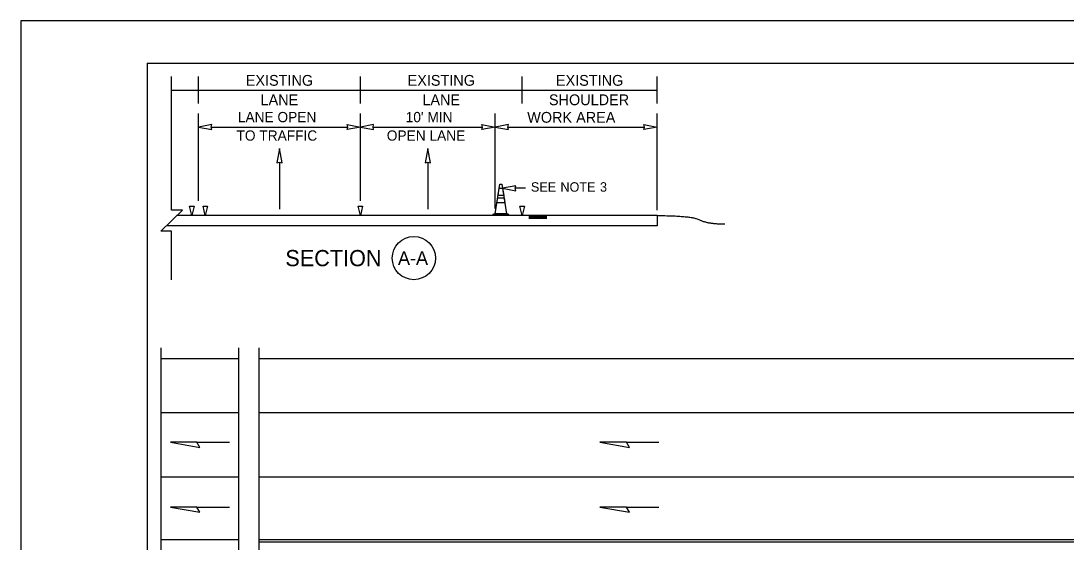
# Model space of a CAD drawing. Extents: x 99999.1 to 100096.1, y 99995 to 100010.7.
# Drawn here: x 100059.06 to 100066.81, y 100006.83 to 100010.69 of the extents above; entities that cross this region are included whole.
import ezdxf

# ---------------------------------------------------------------- set-up
doc = ezdxf.new("R2010")
doc.units = 0
for name, color, linetype in [('RD_ED_ShoulderPavedEdge', 7, 'Continuous'), ('RD_MK_LineEdgeWhite', 7, 'Continuous'), ('RD_MK_LineLane', 7, 'Continuous'), ('RD_MK_LineTwoWayLtTurn', 7, 'Continuous'), ('SH_GI_PlotLimits', 7, 'Continuous'), ('SH_GI_SheetBorder', 7, 'Continuous'), ('SH_TI_WZSectionCut', 7, 'Continuous'), ('TR_WZ_ArrowLeftStrRightTurn', 7, 'Continuous'), ('TR_WZ_TrafficConeElev', 7, 'Continuous'), ('TR_WZ_WorkZoneDetails', 7, 'Continuous'), ('TR_WZ_WorkZoneTextCurrent', 7, 'Continuous')]:
    doc.layers.add(name, color=color, linetype=linetype)

msp = doc.modelspace()

# ---------------------------------------------------------------- linework, layer by layer
at = {"layer": 'RD_ED_ShoulderPavedEdge'}
for p, q in [((100060.1016, 100008.1857), (100060.6783, 100008.1857)), ((100060.8283, 100008.1857), (100074.8933, 100008.1857))]:
    msp.add_line(p, q, dxfattribs=at)
at = {"layer": 'RD_MK_LineEdgeWhite'}
for p, q in [((100060.1016, 100007.7857), (100060.6783, 100007.7857)), ((100060.8283, 100007.7857), (100074.8933, 100007.7857))]:
    msp.add_line(p, q, dxfattribs=at)
at = {"layer": 'RD_MK_LineLane'}
for points in [[(100060.6783, 100007.3057), (100060.1016, 100007.3057)], [(100060.6783, 100007.3057), (100060.1016, 100007.3057)], [(100074.8933, 100007.3057), (100060.8283, 100007.3057)]]:
    msp.add_lwpolyline(points, dxfattribs=at)
at = {"layer": 'RD_MK_LineTwoWayLtTurn'}
for p, q in [((100060.1016, 100006.8457), (100060.6783, 100006.8457)), ((100060.8283, 100006.8457), (100074.914, 100006.8457))]:
    msp.add_line(p, q, dxfattribs=at)
msp.add_lwpolyline([(100074.8933, 100006.8257), (100060.8283, 100006.8257)], dxfattribs=at)
at = {"layer": 'SH_GI_PlotLimits'}
msp.add_lwpolyline([(100059.0625, 99999.6875), (100076.0625, 99999.6875), (100076.0625, 100010.6875), (100059.0625, 100010.6875)], close=True, dxfattribs=at)
at = {"layer": 'SH_GI_SheetBorder'}
for q in [(100060, 100000), (100075.75, 100010.375)]:
    msp.add_line((100060, 100010.375), q, dxfattribs=at)
at = {"layer": 'SH_TI_WZSectionCut'}
for p, q in [((100060.38, 100010.075), (100060.38, 100010.275)), ((100061.58, 100010.075), (100061.58, 100010.275)), ((100062.78, 100010.075), (100062.78, 100010.275)), ((100063.78, 100010.075), (100063.78, 100010.275)), ((100060.18, 100010.175), (100060.38, 100010.175)), ((100060.38, 100010.175), (100061.58, 100010.175)), ((100061.58, 100010.175), (100062.78, 100010.175)), ((100062.78, 100010.175), (100063.78, 100010.175)), ((100060.38, 100009.3547), (100060.38, 100010.001)), ((100061.58, 100009.3547), (100061.58, 100010.001)), ((100062.58, 100009.2975), (100062.58, 100010.001)), ((100063.78, 100009.2849), (100063.78, 100010.001)), ((100060.4738, 100009.901), (100061.4863, 100009.901)), ((100061.6738, 100009.901), (100062.4863, 100009.901)), ((100062.6738, 100009.901), (100063.6863, 100009.901)), ((100063.78, 100009.2449), (100060.2188, 100009.2449)), ((100062.963, 100009.2393), (100062.83, 100009.2393)), ((100062.963, 100009.2337), (100062.83, 100009.2337)), ((100062.963, 100009.228), (100062.83, 100009.228)), ((100062.963, 100009.2228), (100062.83, 100009.2228)), ((100063.78, 100009.2449), (100063.78, 100009.1699)), ((100063.78, 100009.1699), (100060.1413, 100009.1699))]:
    msp.add_line(p, q, dxfattribs=at)
for points in [[(100060.38, 100009.901), (100060.4783, 100009.8817), (100060.4738, 100009.901), (100060.4783, 100009.9203)], [(100061.58, 100009.901), (100061.4817, 100009.8817), (100061.4863, 100009.901), (100061.4817, 100009.9203)], [(100061.58, 100009.901), (100061.6783, 100009.8817), (100061.6738, 100009.901), (100061.6783, 100009.9203)], [(100062.58, 100009.901), (100062.4817, 100009.8817), (100062.4863, 100009.901), (100062.4817, 100009.9203)], [(100062.58, 100009.901), (100062.6783, 100009.8817), (100062.6738, 100009.901), (100062.6783, 100009.9203)], [(100063.78, 100009.901), (100063.6817, 100009.8817), (100063.6863, 100009.901), (100063.6817, 100009.9203)], [(100060.3133, 100009.3147), (100060.3467, 100009.3147), (100060.33, 100009.2449)], [(100060.4133, 100009.3147), (100060.4467, 100009.3147), (100060.43, 100009.2449)], [(100061.5634, 100009.3147), (100061.5967, 100009.3147), (100061.5801, 100009.2449)], [(100062.7634, 100009.3147), (100062.7967, 100009.3147), (100062.7801, 100009.2449)]]:
    msp.add_lwpolyline(points, close=True, dxfattribs=at)
msp.add_circle((100061.9766, 100008.93), 0.16, dxfattribs=at)
msp.add_open_spline([(100063.78, 100009.2449), (100064.0312, 100009.2451), (100064.1567, 100009.183), (100064.2822, 100009.1831)], degree=2, dxfattribs=at)
at = {"layer": 'TR_WZ_ArrowLeftStrRightTurn'}
for p, q in [((100060.98, 100009.6418), (100060.98, 100009.292)), ((100062.08, 100009.6418), (100062.08, 100009.292))]:
    msp.add_line(p, q, dxfattribs=at)
for points in [[(100060.98, 100009.742), (100060.9594, 100009.6369), (100060.98, 100009.6418), (100061.0006, 100009.6369)], [(100062.08, 100009.742), (100062.0594, 100009.6369), (100062.08, 100009.6418), (100062.1006, 100009.6369)]]:
    msp.add_lwpolyline(points, close=True, dxfattribs=at)
at = {"layer": 'TR_WZ_TrafficConeElev'}
for p, q in [((100062.6008, 100009.3929), (100062.6091, 100009.4471)), ((100062.6091, 100009.4471), (100062.6343, 100009.4471)), ((100062.6343, 100009.4471), (100062.6426, 100009.3929)), ((100062.5925, 100009.3388), (100062.5982, 100009.3763)), ((100062.6509, 100009.3388), (100062.5925, 100009.3388)), ((100062.5982, 100009.3763), (100062.6452, 100009.3763)), ((100062.6426, 100009.3929), (100062.6008, 100009.3929)), ((100062.6452, 100009.3763), (100062.6509, 100009.3388)), ((100062.5639, 100009.2533), (100062.5681, 100009.2575)), ((100062.5639, 100009.245), (100062.5639, 100009.2533)), ((100062.6634, 100009.2575), (100062.6753, 100009.2575)), ((100062.6753, 100009.2575), (100062.6795, 100009.2533)), ((100062.6795, 100009.2533), (100062.6795, 100009.245)), ((100062.6795, 100009.245), (100062.5639, 100009.245))]:
    msp.add_line(p, q, dxfattribs=at)
msp.add_lwpolyline([(100062.6634, 100009.2575), (100062.58, 100009.2575), (100062.6139, 100009.4783), (100062.6295, 100009.4783)], close=True, dxfattribs=at)
msp.add_lwpolyline([(100062.6634, 100009.2575), (100062.58, 100009.2575), (100062.6139, 100009.4783), (100062.6295, 100009.4783)], close=True, dxfattribs=at)
msp.add_lwpolyline([(100062.5681, 100009.2575), (100062.58, 100009.2575), (100062.6634, 100009.2575)], dxfattribs=at)
at = {"layer": 'TR_WZ_WorkZoneDetails'}
for p, q in [((100062.8043, 100009.4471), (100062.7281, 100009.4471)), ((100060.3677, 100007.565), (100060.6088, 100007.565)), ((100063.553, 100007.565), (100063.7941, 100007.565)), ((100060.3677, 100007.085), (100060.6088, 100007.085)), ((100063.553, 100007.085), (100063.7941, 100007.085))]:
    msp.add_line(p, q, dxfattribs=at)
for points in [[(100060.18, 100008.7701), (100060.18, 100009.13), (100060.1, 100009.13), (100060.2601, 100009.2849), (100060.18, 100009.2849), (100060.18, 100010.275)], [(100060.1016, 100004.9057), (100060.1016, 100006.5083), (100060.0216, 100006.5083), (100060.1817, 100006.6632), (100060.1016, 100006.6632), (100060.1016, 100008.2657)], [(100060.6783, 100004.9057), (100060.6783, 100006.5083), (100060.5983, 100006.5083), (100060.7583, 100006.6632), (100060.6783, 100006.6632), (100060.6783, 100008.2657)], [(100060.8283, 100004.9057), (100060.8283, 100006.5083), (100060.7483, 100006.5083), (100060.9083, 100006.6632), (100060.8283, 100006.6632), (100060.8283, 100008.2657)]]:
    msp.add_lwpolyline(points, dxfattribs=at)
for points in [[(100062.6343, 100009.4471), (100062.7326, 100009.4279), (100062.728, 100009.4472), (100062.7326, 100009.4664)], [(100060.1712, 100007.565), (100060.39, 100007.5264), (100060.3677, 100007.565)], [(100063.3565, 100007.565), (100063.5753, 100007.5264), (100063.553, 100007.565)], [(100060.1712, 100007.085), (100060.39, 100007.0464), (100060.3677, 100007.085)], [(100063.3565, 100007.085), (100063.5753, 100007.0464), (100063.553, 100007.085)]]:
    msp.add_lwpolyline(points, close=True, dxfattribs=at)

# ---------------------------------------------------------------- texts
at = {"layer": 'SH_TI_WZSectionCut'}
for s, height, p in [('EXISTING', 0.08, (100060.7302, 100010.207)), ('EXISTING', 0.08, (100061.9302, 100010.207)), ('EXISTING', 0.08, (100063.0302, 100010.207)), ('LANE', 0.08, (100060.8396, 100010.063)), ('LANE', 0.08, (100062.0396, 100010.063)), ('SHOULDER', 0.08, (100062.9783, 100010.063)), ('SECTION', 0.12, (100061.0235, 100008.87)), ('A-A', 0.1, (100061.8587, 100008.88))]:
    msp.add_text(s, height=height, rotation=360, dxfattribs=at).set_placement(p)
for s, height, p in [('LANE OPEN', 0.076, (100060.6714, 100009.937)), ("10' MIN", 0.076, (100061.9161, 100009.937)), ('WORK AREA', 0.08, (100062.8171, 100009.933)), ('TO TRAFFIC', 0.076, (100060.6613, 100009.8002)), ('OPEN LANE', 0.076, (100061.7758, 100009.8002))]:
    msp.add_text(s, height=height, dxfattribs=at).set_placement(p)
at = {"layer": 'TR_WZ_WorkZoneTextCurrent'}
for s, p in [('SEE', (100062.8443, 100009.4221)), ('NOTE', (100063.0635, 100009.4221)), ('3', (100063.3567, 100009.4221))]:
    msp.add_text(s, height=0.07, dxfattribs=at).set_placement(p)

doc.saveas('drawing.dxf')
